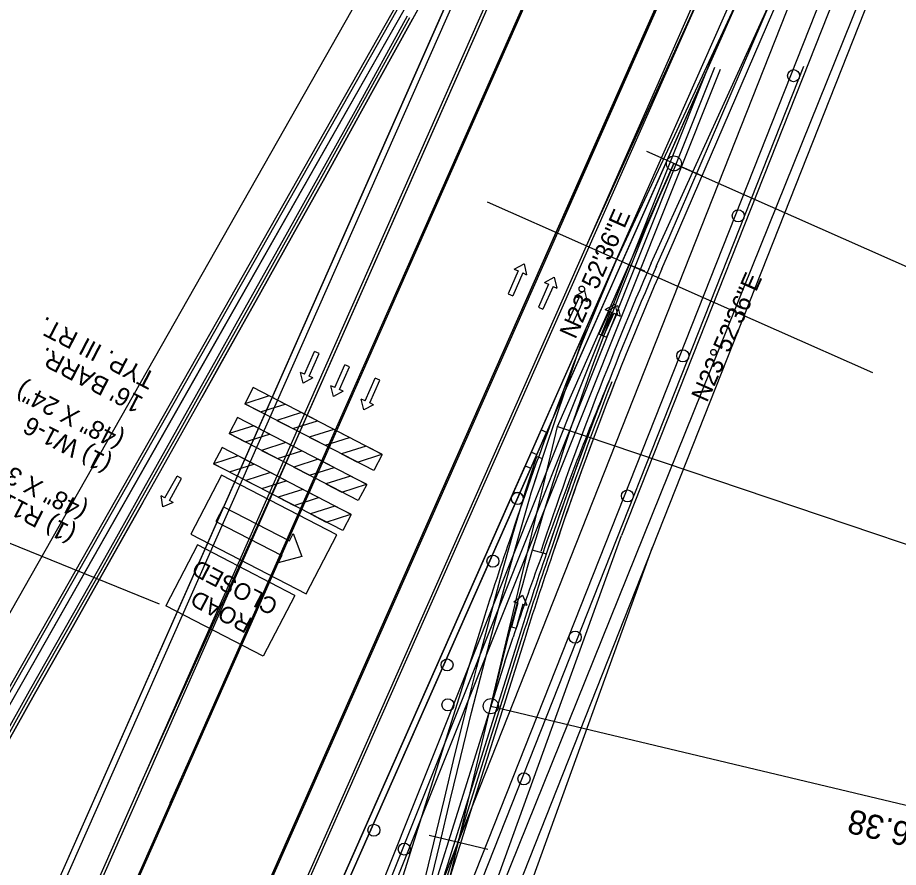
# Model space of a CAD drawing. Extents: x 659657 to 668193, y 633084 to 648639.
# Drawn here: x 662475.1 to 662767.5, y 643378.9 to 643660.9 of the extents above; entities that cross this region are included whole.
import ezdxf

# ---------------------------------------------------------------- set-up
doc = ezdxf.new("R2010")
doc.units = 0
for name, color, linetype in [('R_Border Prem', 7, 'Continuous'), ('R_Draft', 7, 'Continuous'), ('R_MOT_Stage 1A', 7, 'Continuous'), ('R_MOT_Stage 1A_Striping', 7, 'Continuous'), ('R_MOT_Stage 1B', 7, 'Continuous'), ('R_MOT_Stage 1B_Striping', 7, 'Continuous'), ('R_MOT_Stage 1C', 7, 'Continuous'), ('R_MOT_Stage 1C_Striping', 7, 'Continuous'), ('R_MOT_Stage 1C_Striping_PPM', 7, 'Continuous'), ('R_MOT_Stage 2', 7, 'Continuous'), ('R_MOT_Stage 2_Striping', 7, 'Continuous'), ('R_MOT_Stage 2_Striping_PPM', 7, 'Continuous'), ('R_MOT_Stage 3', 7, 'Continuous'), ('R_MOT_Stage 3_Striping', 7, 'Continuous'), ('R_MOT_Stage 3_Striping_PPM', 7, 'Continuous'), ('R_MOT_Stage 4', 7, 'Continuous'), ('R_MOT_Stage 4_Striping', 7, 'Continuous'), ('R_MOT_Stage 4_Striping_PPM', 7, 'Continuous'), ('R_MOT_Stage 5_Striping_PPM', 7, 'Continuous'), ('T_SIGNAL CONTROL CABINET', 7, 'Continuous')]:
    doc.layers.add(name, color=color, linetype=linetype)

msp = doc.modelspace()

# ---------------------------------------------------------------- linework, layer by layer
at = {"layer": 'R_Border Prem'}
msp.add_line((661686.79, 641562.92), (662861.91, 644217.67), dxfattribs=at)
at = {"layer": 'R_Draft'}
for p, q in [((662534.43, 643549.33), (662534.38, 643549.31)), ((662553.31, 643538.15), (662550.53, 643532.78)), ((662596.18, 643515.94), (662553.31, 643538.15)), ((662593.4, 643510.57), (662550.53, 643532.78)), ((662548.16, 643528.2), (662545.38, 643522.84)), ((662591.03, 643505.99), (662548.16, 643528.2)), ((662588.25, 643500.63), (662545.38, 643522.84)), ((662543, 643518.24), (662540.21, 643512.86)), ((662585.87, 643496.03), (662543, 643518.24)), ((662596.18, 643515.94), (662593.4, 643510.57)), ((662583.08, 643490.65), (662540.21, 643512.86)), ((662416.93, 643509.09), (662522.12, 643466.36)), ((662591.03, 643505.99), (662588.25, 643500.63)), ((662543.52, 643498.55), (662541, 643493.68)), ((662543.52, 643498.55), (662565.38, 643487.22)), ((662585.87, 643496.03), (662583.08, 643490.65)), ((662541, 643493.68), (662562.86, 643482.36)), ((662565.38, 643487.22), (662566.64, 643489.66)), ((662566.64, 643489.66), (662569.46, 643482.02)), ((662534.85, 643485.93), (662524.39, 643465.74)), ((662567.17, 643469.18), (662534.85, 643485.93)), ((662562.86, 643482.36), (662561.6, 643479.92)), ((662569.46, 643482.02), (662561.6, 643479.92)), ((662567.17, 643469.18), (662556.71, 643448.99)), ((662556.71, 643448.99), (662524.39, 643465.74))]:
    msp.add_line(p, q, dxfattribs=at)
for points in [[(662550.53, 643532.78), (662555.81, 643530.07), (662563.93, 643532.65), (662558.68, 643535.37)], [(662561.25, 643527.23), (662566.52, 643524.52), (662574.65, 643527.1), (662569.39, 643529.82)], [(662545.38, 643522.84), (662550.66, 643520.12), (662558.78, 643522.7), (662553.53, 643525.42)], [(662571.96, 643521.68), (662577.23, 643518.97), (662585.36, 643521.55), (662580.1, 643524.27)], [(662556.09, 643517.29), (662561.37, 643514.57), (662569.49, 643517.15), (662564.24, 643519.87)], [(662582.67, 643516.13), (662587.95, 643513.42), (662596.07, 643516), (662590.81, 643518.72)], [(662540.21, 643512.86), (662545.49, 643510.15), (662553.61, 643512.72), (662548.36, 643515.45)], [(662566.8, 643511.74), (662572.08, 643509.02), (662580.2, 643511.6), (662574.95, 643514.32)], [(662550.92, 643507.31), (662556.2, 643504.6), (662564.32, 643507.17), (662559.07, 643509.9)], [(662581.12, 643489.23), (662542.79, 643509.09), (662532.63, 643489.49), (662570.96, 643469.63)], [(662577.51, 643506.19), (662582.79, 643503.47), (662590.92, 643506.05), (662585.66, 643508.77)], [(662561.63, 643501.76), (662566.91, 643499.05), (662575.03, 643501.62), (662569.78, 643504.35)], [(662572.35, 643496.21), (662577.62, 643493.5), (662585.75, 643496.08), (662580.49, 643498.8)]]:
    msp.add_lwpolyline(points, close=True, dxfattribs=at)
at = {"layer": 'R_MOT_Stage 1A'}
for p, q in [((662556.65, 643315.57), (662645.7, 643516.74)), ((662558.48, 643314.76), (662647.53, 643515.93)), ((662647.54, 643515.26), (662649.44, 643514.64))]:
    msp.add_line(p, q, dxfattribs=at)
for points in [[(662643.18, 643501.74), (662643.76, 643503.74), (662647.54, 643515.26)], [(662645.7, 643516.74), (662647.53, 643515.93)], [(662645.11, 643501.18), (662645.68, 643503.15), (662649.44, 643514.64)], [(662609.82, 643372.44), (662613.33, 643387.02), (662616.81, 643401.61), (662620.29, 643416.2), (662623.93, 643430.75), (662627.6, 643445.3), (662631.44, 643459.81), (662635.47, 643474.89), (662639.59, 643489.32), (662643.18, 643501.74)], [(662611.76, 643371.97), (662615.27, 643386.56), (662618.76, 643401.15), (662622.24, 643415.73), (662625.87, 643430.27), (662629.54, 643444.8), (662633.37, 643459.29), (662637.4, 643474.35), (662641.52, 643488.77), (662645.11, 643501.18)]]:
    msp.add_lwpolyline(points, dxfattribs=at)
at = {"layer": 'R_MOT_Stage 1A_Striping'}
for p, q in [((662653.91, 643589.66), (662694.85, 643680.89)), ((662663.97, 643585.2), (662705.36, 643676.24)), ((662654.38, 643525.25), (662693.02, 643612.53)), ((662654.38, 643525.25), (662693.02, 643612.53)), ((662654.38, 643525.25), (662693.02, 643612.53)), ((662516.29, 643278.75), (662653.91, 643589.66)), ((662526.35, 643274.3), (662663.97, 643585.2)), ((662632.25, 643432.4), (662654.38, 643525.25)), ((662556.65, 643315.57), (662645.7, 643516.74)), ((662545.19, 643067.11), (662632.25, 643432.4))]:
    msp.add_line(p, q, dxfattribs=at)
for points in [[(662683.88, 643616.58), (662702.16, 643608.48)], [(662693.02, 643612.53), (662910.17, 643516.41)], [(662683.38, 643576.81), (662678.74, 643578.67)], [(662645.11, 643501.18), (662645.68, 643503.15), (662650.33, 643517.37), (662664.01, 643558.12)], [(662645.7, 643516.74), (662664.01, 643558.12)], [(662654.38, 643525.25), (662873.39, 643451.37)], [(662611.76, 643371.97), (662615.27, 643386.56), (662618.76, 643401.15), (662622.24, 643415.73), (662625.87, 643430.27), (662629.54, 643444.8), (662633.37, 643459.29), (662637.4, 643474.35), (662641.52, 643488.77), (662645.11, 643501.18)], [(662650.82, 643482.81), (662646.02, 643484.21)], [(662632.25, 643432.4), (662852.82, 643379.83)], [(662611.77, 643389.6), (662631.23, 643384.96)]]:
    msp.add_lwpolyline(points, dxfattribs=at)
for centre in [(662693.02, 643612.53), (662632.25, 643432.4)]:
    msp.add_circle(centre, 2.5, dxfattribs=at)
msp.add_arc((663645.61, 643190.87), 1041.74, 156.12343, 166.59359, dxfattribs=at)
at = {"layer": 'R_MOT_Stage 1B'}
for p, q in [((662691.44, 643587.95), (662731.76, 643681.52)), ((662693.27, 643587.15), (662733.59, 643680.71)), ((662687.17, 643578.32), (662691.44, 643587.95)), ((662689, 643577.51), (662693.27, 643587.15)), ((662641.39, 643454.72), (662559.48, 643194.07)), ((662643.3, 643454.12), (662561.39, 643193.47))]:
    msp.add_line(p, q, dxfattribs=at)
for centre in [(662641.06, 643501.33), (662632.95, 643480.53), (662617.7, 643446.08), (662617.99, 643432.83), (662593.42, 643391.22), (662603.52, 643384.97)]:
    msp.add_circle(centre, 2, dxfattribs=at)
for centre, radius, start, end in [((663731.71, 643123.84), 1139.12, 156.48215, 161.61439), ((663731.5, 643123.92), 1136.9, 156.48171, 161.61494), ((663731.71, 643123.84), 1139.12, 158.55134, 161.61439), ((663731.5, 643123.92), 1136.9, 158.55364, 161.61494), ((662641.06, 643501.33), 2, 340.9089, 156.1234), ((663727.44, 643113.43), 1138.42, 161.04926, 162.55479), ((663727.44, 643113.43), 1136.42, 161.04826, 162.55479)]:
    msp.add_arc(centre, radius, start, end, dxfattribs=at)
at = {"layer": 'R_MOT_Stage 1B_Striping'}
for p, q in [((662653.91, 643589.66), (662920.44, 644191.76)), ((662663.97, 643585.2), (662930.5, 644187.31)), ((662675.28, 643583.58), (662795.46, 643855.08)), ((662654.38, 643525.25), (662693.02, 643612.53)), ((662654.38, 643525.25), (662693.02, 643612.53)), ((662654.38, 643525.25), (662693.02, 643612.53)), ((662532.48, 643315.33), (662653.91, 643589.66)), ((662542.54, 643310.88), (662663.97, 643585.2)), ((662664.01, 643558.12), (662675.28, 643583.58)), ((662639.23, 643502.14), (662664.01, 643558.12)), ((662632.25, 643432.4), (662654.38, 643525.25)), ((662552.6, 643306.42), (662639.23, 643502.14)), ((662628.99, 643458.62), (662547.08, 643197.97)), ((662636.91, 643447.13), (662639.64, 643455.27)), ((662636.91, 643447.13), (662557.57, 643194.67)), ((662545.19, 643067.11), (662632.25, 643432.4))]:
    msp.add_line(p, q, dxfattribs=at)
for points in [[(662685.48, 643579.45), (662726.99, 643670.44), (662731.76, 643681.52)], [(662683.88, 643616.58), (662702.16, 643608.48)], [(662693.02, 643612.53), (662910.17, 643516.41)], [(662683.38, 643576.81), (662678.74, 643578.67)], [(662654.38, 643525.25), (662873.39, 643451.37)], [(662650.82, 643482.81), (662646.02, 643484.21)], [(662632.25, 643432.4), (662852.82, 643379.83)], [(662611.77, 643389.6), (662631.23, 643384.96)]]:
    msp.add_lwpolyline(points, dxfattribs=at)
for centre in [(662693.02, 643612.53), (662632.25, 643432.4)]:
    msp.add_circle(centre, 2.5, dxfattribs=at)
for centre, radius, start, end in [((663645.61, 643190.87), 1041.74, 156.12343, 166.59359), ((663731.5, 643123.92), 1151.9, 156.48171, 159.46645), ((663731.5, 643123.92), 1140.9, 156.4674, 161.61395), ((663724.79, 643102), 1140.9, 157.39892, 160.46312), ((663731.5, 643123.92), 1151.9, 159.46645, 161.61126), ((663727.44, 643113.43), 1151.42, 161.05195, 162.55479), ((663720.52, 643091.59), 1140.42, 159.89842, 161.40396)]:
    msp.add_arc(centre, radius, start, end, dxfattribs=at)
at = {"layer": 'R_MOT_Stage 1C'}
for centre in [(662732.77, 643641.64), (662714.38, 643595.14), (662695.98, 643548.65), (662677.59, 643502.16), (662660.24, 643455.3), (662643.25, 643408.28)]:
    msp.add_circle(centre, 2, dxfattribs=at)
at = {"layer": 'R_MOT_Stage 1C_Striping'}
for p, q in [((662795.88, 643793.01), (662675.65, 643489.09)), ((662492.46, 643223.68), (662694.85, 643680.89)), ((662502.98, 643219.03), (662705.36, 643676.24)), ((662513.95, 643214.17), (662716.34, 643671.38)), ((662596.14, 643269.11), (662675.65, 643489.09)), ((662606.43, 643265.22), (662685.93, 643485.2))]:
    msp.add_line(p, q, dxfattribs=at)
at = {"layer": 'R_MOT_Stage 1C_Striping_PPM'}
msp.add_line((662806.18, 643789.14), (662685.93, 643485.2), dxfattribs=at)
at = {"layer": 'R_MOT_Stage 2'}
for points in [[(662645.5, 643511.36), (662650.76, 643523.25), (662648.94, 643524.06), (662643.67, 643512.17)], [(662645.5, 643511.36), (661880.49, 641783.11), (661878.66, 641783.92), (662643.67, 643512.17)]]:
    msp.add_lwpolyline(points, close=True, dxfattribs=at)
for centre in [(662732.77, 643641.64), (662714.38, 643595.14), (662695.98, 643548.65), (662677.59, 643502.16), (662660.24, 643455.3), (662643.25, 643408.28)]:
    msp.add_circle(centre, 2, dxfattribs=at)
at = {"layer": 'R_MOT_Stage 2_Striping'}
for p, q in [((662795.88, 643793.01), (662675.65, 643489.09)), ((662694.85, 643680.89), (662653.91, 643589.66)), ((662663.97, 643585.2), (662705.36, 643676.24)), ((662716.34, 643671.38), (662674.03, 643580.75)), ((662653.91, 643589.66), (661803.9, 641669.37)), ((661813.96, 641664.92), (662663.97, 643585.2)), ((662596.14, 643269.11), (662675.65, 643489.09)), ((662606.43, 643265.22), (662685.93, 643485.2))]:
    msp.add_line(p, q, dxfattribs=at)
msp.add_lwpolyline([(661878.66, 641783.92), (662674.03, 643580.75)], dxfattribs=at)
at = {"layer": 'R_MOT_Stage 2_Striping_PPM'}
msp.add_line((662806.18, 643789.14), (662685.93, 643485.2), dxfattribs=at)
at = {"layer": 'R_MOT_Stage 3'}
for p, q in [((662610.32, 643667.76), (662606.27, 643660.43)), ((662606.27, 643660.43), (662588.8, 643628.82)), ((662595.25, 643365.71), (662706.63, 643644.52)), ((662597.09, 643364.94), (662708.49, 643643.78)), ((662588.8, 643628.82), (662577.16, 643607.76)), ((662577.16, 643607.76), (662566.53, 643588.78)), ((662566.53, 643588.78), (662555.91, 643569.81)), ((662555.91, 643569.81), (662549.37, 643558.16)), ((662549.37, 643558.16), (662536.28, 643534.86)), ((662529.74, 643523.21), (662536.28, 643534.86)), ((662523.23, 643511.63), (662529.74, 643523.21)), ((662516.72, 643500.04), (662523.23, 643511.63)), ((662516.72, 643500.04), (662503.7, 643476.88)), ((662503.7, 643476.88), (662492.23, 643456.65)), ((662492.23, 643456.65), (662480.76, 643436.42)), ((662480.76, 643436.42), (662468.89, 643415.34))]:
    msp.add_line(p, q, dxfattribs=at)
msp.add_lwpolyline([(662604.52, 643661.39), (662587.05, 643629.78), (662575.41, 643608.73), (662564.79, 643589.76), (662554.16, 643570.78), (662547.62, 643559.14), (662541.08, 643547.48), (662534.54, 643535.83), (662528, 643524.19), (662521.49, 643512.61), (662514.98, 643501.03), (662508.47, 643489.45), (662501.96, 643477.86), (662490.49, 643457.64), (662479.02, 643437.41), (662467.15, 643416.33), (662455.27, 643395.24), (662446.58, 643379.89), (662437.88, 643364.53)], dxfattribs=at)
at = {"layer": 'R_MOT_Stage 3_Striping'}
for p, q in [((662566.8, 643518.86), (662873.8, 644212.41)), ((662566.8, 643518.86), (662873.8, 644212.41)), ((662576.86, 643514.4), (662883.86, 644207.95)), ((662576.86, 643514.4), (662883.86, 644207.95)), ((662792.14, 643794.42), (662622.73, 643366.22)), ((662704.78, 643645.27), (662716.34, 643671.38)), ((662593.4, 643366.49), (662704.78, 643645.27)), ((662515.29, 643404.96), (662566.8, 643518.86)), ((662525.81, 643400.3), (662576.86, 643514.4))]:
    msp.add_line(p, q, dxfattribs=at)
for points in [[(662603.12, 643654.73), (662610.32, 643667.76), (662626.17, 643697.36), (662638.02, 643719.78), (662647.95, 643738.69), (662656.45, 643755.53), (662664.54, 643771.77)], [(662439.62, 643363.54), (662448.32, 643378.9), (662457.01, 643394.26), (662468.89, 643415.34), (662480.76, 643436.42), (662492.23, 643456.65), (662503.7, 643476.88), (662510.21, 643488.46), (662516.72, 643500.04), (662523.23, 643511.63), (662529.74, 643523.21), (662536.28, 643534.86), (662542.83, 643546.51), (662549.37, 643558.16), (662555.91, 643569.81), (662566.53, 643588.78), (662577.16, 643607.76), (662588.8, 643628.82), (662606.27, 643660.43)]]:
    msp.add_lwpolyline(points, dxfattribs=at)
at = {"layer": 'R_MOT_Stage 3_Striping_PPM'}
for p, q in [((662806.18, 643789.14), (662685.93, 643485.2)), ((661859, 641792.62), (662694.85, 643680.89)), ((661869.52, 641787.96), (662705.36, 643676.24)), ((662685.93, 643485.2), (662636.76, 643360.91))]:
    msp.add_line(p, q, dxfattribs=at)
at = {"layer": 'R_MOT_Stage 4'}
for p, q in [((662482.06, 643359.52), (662648.01, 643734.43)), ((662483.88, 643358.71), (662649.84, 643733.63)), ((662454.93, 643406), (662629.22, 643712.99)), ((662456.67, 643405.01), (662630.96, 643712))]:
    msp.add_line(p, q, dxfattribs=at)
at = {"layer": 'R_MOT_Stage 4_Striping'}
for p, q in [((662792.14, 643794.42), (662622.73, 643366.22)), ((662475.79, 643340.42), (662672.54, 643784.91)), ((662704.78, 643645.27), (662716.34, 643671.38)), ((662593.4, 643366.49), (662704.78, 643645.27))]:
    msp.add_line(p, q, dxfattribs=at)
for points in [[(662485.93, 643336.15), (662688.23, 643793.18), (662727.79, 643885.03)], [(662495.91, 643331.52), (662698.29, 643788.73), (662738.31, 643880.37)], [(662431.31, 643361.56), (662454.07, 643406.49), (662628.36, 643713.48)]]:
    msp.add_lwpolyline(points, dxfattribs=at)
at = {"layer": 'R_MOT_Stage 4_Striping_PPM'}
for p, q in [((662806.18, 643789.14), (662685.93, 643485.2)), ((662437.27, 643401.21), (662617.92, 643719.41)), ((661859, 641792.62), (662694.85, 643680.89)), ((661869.52, 641787.96), (662705.36, 643676.24)), ((662685.93, 643485.2), (662636.76, 643360.91))]:
    msp.add_line(p, q, dxfattribs=at)
at = {"layer": 'R_MOT_Stage 5_Striping_PPM'}
for p, q in [((662572.57, 643263.89), (662866.47, 644006.76)), ((662572.57, 643263.89), (662866.47, 644006.76)), ((662572.57, 643263.89), (662866.47, 644006.76)), ((662444.46, 643244.94), (662727.79, 643885.03)), ((662454.97, 643240.28), (662738.31, 643880.37)), ((662806.18, 643789.14), (662685.93, 643485.2)), ((662437.27, 643401.21), (662617.92, 643719.41)), ((662534.07, 643541.34), (662630.96, 643712)), ((661859, 641792.62), (662694.85, 643680.89)), ((661869.52, 641787.96), (662705.36, 643676.24)), ((662215.01, 642538.82), (662716.34, 643671.38)), ((662450.31, 643393.81), (662534.07, 643541.34)), ((662685.93, 643485.2), (662636.76, 643360.91)), ((662433.48, 643249.79), (662518.92, 643442.81))]:
    msp.add_line(p, q, dxfattribs=at)
for points in [[(662518.92, 643442.81), (662670.71, 643785.72)], [(662588.74, 643272.15), (662625.61, 643365.32), (662736.19, 643644.85)]]:
    msp.add_lwpolyline(points, dxfattribs=at)
at = {"layer": 'T_SIGNAL CONTROL CABINET'}
for p, q in [((662619.44, 643331.41), (662810.32, 643804.65)), ((662619.45, 643331.46), (662810.32, 643804.65)), ((662631.05, 643599.77), (662758.91, 643543.18)), ((662689, 643577.51), (662693.27, 643587.15)), ((662689, 643577.51), (662693.27, 643587.15)), ((662641.31, 643576.86), (662637.96, 643569.29)), ((662641.31, 643576.86), (662637.96, 643569.29)), ((662640.02, 643577.43), (662643.26, 643579.19)), ((662640.02, 643577.43), (662643.26, 643579.19)), ((662640.02, 643577.43), (662641.31, 643576.86)), ((662640.02, 643577.43), (662641.31, 643576.86)), ((662643.26, 643579.19), (662644.14, 643575.6)), ((662643.26, 643579.19), (662644.14, 643575.6)), ((662642.85, 643576.17), (662639.5, 643568.61)), ((662642.85, 643576.17), (662639.5, 643568.61)), ((662642.85, 643576.17), (662644.14, 643575.6)), ((662642.85, 643576.17), (662644.14, 643575.6)), ((662650.08, 643572.97), (662653.32, 643574.73)), ((662650.08, 643572.97), (662653.32, 643574.73)), ((662653.32, 643574.73), (662654.2, 643571.15)), ((662653.32, 643574.73), (662654.2, 643571.15)), ((662651.37, 643572.4), (662648.02, 643564.84)), ((662651.37, 643572.4), (662648.02, 643564.84)), ((662652.91, 643571.72), (662649.56, 643564.15)), ((662652.91, 643571.72), (662649.56, 643564.15)), ((662650.08, 643572.97), (662651.37, 643572.4)), ((662650.08, 643572.97), (662651.37, 643572.4)), ((662652.91, 643571.72), (662654.2, 643571.15)), ((662652.91, 643571.72), (662654.2, 643571.15)), ((662637.96, 643569.29), (662639.5, 643568.61)), ((662637.96, 643569.29), (662639.5, 643568.61)), ((662661.43, 643567.95), (662658.08, 643560.38)), ((662661.43, 643567.95), (662658.08, 643560.38)), ((662660.14, 643568.52), (662663.38, 643570.28)), ((662660.14, 643568.52), (662663.38, 643570.28)), ((662660.14, 643568.52), (662661.43, 643567.95)), ((662660.14, 643568.52), (662661.43, 643567.95)), ((662663.38, 643570.28), (662664.26, 643566.7)), ((662663.38, 643570.28), (662664.26, 643566.7)), ((662662.97, 643567.27), (662659.62, 643559.7)), ((662662.97, 643567.27), (662659.62, 643559.7)), ((662662.97, 643567.27), (662664.26, 643566.7)), ((662662.97, 643567.27), (662664.26, 643566.7)), ((662670.2, 643564.07), (662673.44, 643565.83)), ((662671.12, 643563.66), (662674.35, 643565.42)), ((662673.44, 643565.83), (662674.32, 643562.25)), ((662674.35, 643565.42), (662675.23, 643561.84)), ((662648.02, 643564.84), (662649.56, 643564.15)), ((662648.02, 643564.84), (662649.56, 643564.15)), ((662671.49, 643563.5), (662668.14, 643555.93)), ((662672.4, 643563.09), (662669.05, 643555.53)), ((662673.03, 643562.82), (662669.68, 643555.25)), ((662670.2, 643564.07), (662671.49, 643563.5)), ((662673.94, 643562.41), (662670.59, 643554.84)), ((662671.12, 643563.66), (662672.4, 643563.09)), ((662673.03, 643562.82), (662674.32, 643562.25)), ((662673.94, 643562.41), (662675.23, 643561.84)), ((662658.08, 643560.38), (662659.62, 643559.7)), ((662658.08, 643560.38), (662659.62, 643559.7)), ((662668.14, 643555.93), (662669.68, 643555.25)), ((662669.05, 643555.53), (662670.59, 643554.84)), ((662570.37, 643542.59), (662573.72, 643550.15)), ((662571.91, 643541.9), (662575.26, 643549.47)), ((662575.26, 643549.47), (662573.72, 643550.15)), ((662580.43, 643538.15), (662583.78, 643545.71)), ((662581.98, 643537.46), (662585.33, 643545.03)), ((662585.33, 643545.03), (662583.78, 643545.71)), ((662570.37, 643542.59), (662569.08, 643543.16)), ((662569.96, 643539.57), (662569.08, 643543.16)), ((662573.2, 643541.33), (662571.91, 643541.9)), ((662573.2, 643541.33), (662569.96, 643539.57)), ((662580.43, 643538.15), (662579.15, 643538.72)), ((662580.02, 643535.13), (662579.15, 643538.72)), ((662590.5, 643533.71), (662593.85, 643541.27)), ((662592.04, 643533.02), (662595.39, 643540.59)), ((662595.39, 643540.59), (662593.85, 643541.27)), ((662583.26, 643536.89), (662580.02, 643535.13)), ((662583.26, 643536.89), (662581.98, 643537.46)), ((662590.5, 643533.71), (662589.21, 643534.28)), ((662590.09, 643530.69), (662589.21, 643534.28)), ((662593.33, 643532.45), (662592.04, 643533.02)), ((662593.33, 643532.45), (662590.09, 643530.69)), ((662524.05, 643501.54), (662528.1, 643508.75)), ((662525.52, 643500.71), (662529.58, 643507.92)), ((662529.58, 643507.92), (662528.1, 643508.75)), ((662524.05, 643501.54), (662522.82, 643502.23)), ((662523.35, 643498.58), (662522.82, 643502.23)), ((662526.75, 643500.02), (662525.52, 643500.71)), ((662526.75, 643500.02), (662523.35, 643498.58)), ((662639.85, 643467.05), (662642.77, 643469.29)), ((662642.77, 643469.29), (662644.19, 643465.89)), ((662641.2, 643466.68), (662639.07, 643458.69)), ((662639.85, 643467.05), (662641.2, 643466.68)), ((662642.83, 643466.25), (662640.7, 643458.25)), ((662642.83, 643466.25), (662644.19, 643465.89)), ((662639.07, 643458.69), (662640.7, 643458.25)), ((662642.34, 643454.42), (662560.43, 643193.77))]:
    msp.add_line(p, q, dxfattribs=at)
msp.add_lwpolyline([(662438.75, 643364.03), (662447.45, 643379.39), (662456.14, 643394.75), (662468.02, 643415.83), (662479.89, 643436.91), (662491.36, 643457.14), (662502.83, 643477.37), (662509.34, 643488.95), (662515.85, 643500.53), (662522.36, 643512.12), (662528.87, 643523.7), (662535.41, 643535.35), (662541.95, 643547), (662548.49, 643558.65), (662555.04, 643570.29), (662565.66, 643589.27), (662576.29, 643608.24), (662587.92, 643629.3), (662605.39, 643660.91)], dxfattribs=at)
for centre, radius, start, end in [((663731.71, 643123.84), 1138.12, 158.55241, 161.61439), ((663727.44, 643113.43), 1137.42, 161.04926, 162.55479)]:
    msp.add_arc(centre, radius, start, end, dxfattribs=at)

# ---------------------------------------------------------------- texts
at = {"layer": 'R_Draft'}
for s, height, p in [('TYP. III RT.', 6, (662521.43, 643542.63)), ("16' BARR.", 6, (662517.29, 643534.64)), ('(48" X 24")', 6, (662510.97, 643522.44)), ('(1) W1-6', 6, (662506.83, 643514.45)), ('(48" X 30")', 6, (662498.84, 643499.02)), ('(1) R11-2', 6, (662494.93, 643491.15)), ('CLOSED', 5.537, (662562.02, 643467.23)), ('ROAD', 5.51, (662553.43, 643461.28))]:
    msp.add_text(s, height=height, rotation=152.6108, dxfattribs=at).set_placement(p)
at = {"layer": 'R_MOT_Stage 1A_Striping'}
for s, height, rotation, p in [('N23%%d52\'36"E', 6, 66.1234, (662704.03, 643532.93)), ('P.C. STA. 185+46.38', 8, 166.5936, (662850.52, 643374.81))]:
    msp.add_text(s, height=height, rotation=rotation, dxfattribs=at).set_placement(p)
at = {"layer": 'R_MOT_Stage 1B_Striping'}
for s, height, rotation, p in [('N23%%d52\'36"E', 6, 66.1234, (662660.3, 643553.94)), ('P.C. STA. 185+46.38', 8, 166.5936, (662850.52, 643374.81))]:
    msp.add_text(s, height=height, rotation=rotation, dxfattribs=at).set_placement(p)

doc.saveas('drawing.dxf')
